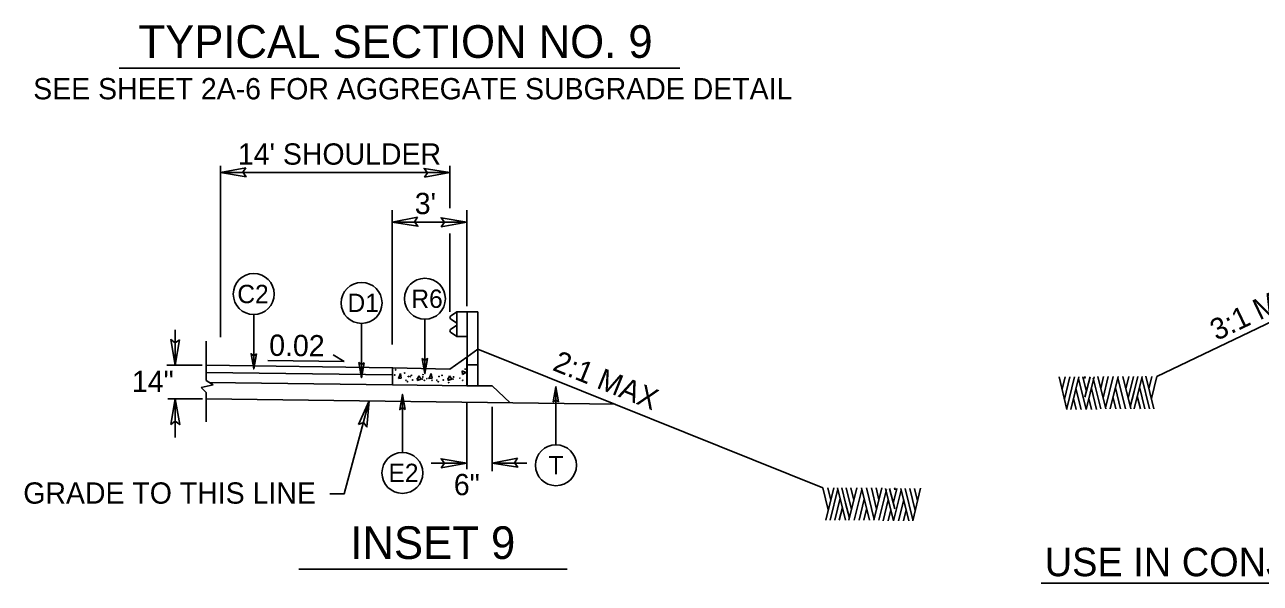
# Model space of a CAD drawing. Extents: x 573748 to 574632, y -54663 to -53209.
# Drawn here: x 574021.1 to 574108.2, y -54255.2 to -54215.9 of the extents above; entities that cross this region are included whole.
import ezdxf

# ---------------------------------------------------------------- set-up
doc = ezdxf.new("R2010")
doc.units = 0
for name, color, linetype in [('Prop Dimension', 7, 'Continuous'), ('Prop Dimension Text', 7, 'Continuous'), ('Prop Terminator CELL', 7, 'Continuous'), ('Typical Arrow Superelevation CELL', 7, 'Continuous'), ('Typical Curb CELL', 7, 'Continuous'), ('Typical Guardrail CELL', 7, 'Continuous'), ('Typical Hinge Slope Arterial CELL', 7, 'Continuous'), ('Typical ID Circle CELL', 7, 'Continuous'), ('Typical Pavement Slope CELL', 7, 'Continuous'), ('Typical Slope Point Local CELL', 7, 'Continuous'), ('Typical Terminator CELL', 7, 'Continuous'), ('Typical Text General CELL', 7, 'Continuous'), ('Typical Text ID Circle CELL', 7, 'Continuous'), ('Typical Text Label CELL', 7, 'Continuous')]:
    doc.layers.add(name, color=color, linetype=linetype)

msp = doc.modelspace()

# ---------------------------------------------------------------- linework, layer by layer
at = {"layer": 'Prop Dimension'}
for p, q in [((574034.928, -54237.862), (574034.928, -54225.799)), ((574051.103, -54228.794), (574051.103, -54225.799)), ((574034.928, -54226.281), (574051.103, -54226.281)), ((574047.036, -54238.382), (574047.036, -54228.937)), ((574052.294, -54235.69), (574052.294, -54228.937)), ((574047.036, -54229.764), (574052.294, -54229.764)), ((574051.103, -54236.089), (574051.103, -54230.577)), ((574031.746, -54237.345), (574031.746, -54239.849)), ((574033.923, -54238.16), (574033.923, -54240.935)), ((574031.151, -54239.849), (574033.652, -54239.849)), ((574034.429, -54241.231), (574033.564, -54241.428)), ((574033.564, -54241.428), (574033.923, -54241.779)), ((574033.923, -54240.935), (574034.429, -54241.231)), ((574031.216, -54242.216), (574033.673, -54242.216)), ((574031.746, -54242.216), (574031.746, -54244.939)), ((574033.923, -54241.779), (574033.923, -54243.831)), ((574052.294, -54247.175), (574052.294, -54242.481)), ((574054.075, -54247.322), (574054.075, -54242.775)), ((574049.783, -54246.736), (574052.294, -54246.736)), ((574054.075, -54246.736), (574056.516, -54246.736))]:
    msp.add_line(p, q, dxfattribs=at)
msp.add_lwpolyline([(574042.641, -54248.905), (574043.662, -54248.905), (574045.423, -54242.368)], dxfattribs=at)
at = {"layer": 'Prop Terminator CELL'}
for points in [[(574036.725, -54225.947), (574034.928, -54226.281), (574036.743, -54226.577), (574036.509, -54226.26)], [(574049.307, -54226.614), (574051.103, -54226.281), (574049.288, -54225.984), (574049.523, -54226.301)], [(574048.833, -54229.431), (574047.036, -54229.764), (574048.851, -54230.061), (574048.617, -54229.744)], [(574050.498, -54230.097), (574052.294, -54229.764), (574050.48, -54229.467), (574050.714, -54229.784)], [(574032.056, -54238.049), (574031.746, -54239.849), (574031.426, -54238.039), (574031.746, -54238.269)], [(574031.436, -54244.016), (574031.746, -54242.216), (574032.066, -54244.026), (574031.746, -54243.796)], [(574044.655, -54244.026), (574045.423, -54242.368), (574045.261, -54244.2), (574045.011, -54243.894)], [(574050.498, -54247.07), (574052.294, -54246.736), (574050.48, -54246.44), (574050.714, -54246.757)], [(574055.871, -54246.403), (574054.075, -54246.736), (574055.889, -54247.033), (574055.655, -54246.716)]]:
    msp.add_lwpolyline(points, close=True, dxfattribs=at)
at = {"layer": 'Typical Arrow Superelevation CELL'}
for q in [(574038.268, -54239.526), (574042.875, -54239.124)]:
    msp.add_line((574043.662, -54239.591), q, dxfattribs=at)
at = {"layer": 'Typical Curb CELL'}
for p, q in [((574052.294, -54239.272), (574053.079, -54238.708)), ((574051.103, -54240.129), (574052.294, -54239.272)), ((574052.294, -54241.296), (574052.294, -54239.272)), ((574047.06, -54240.024), (574047.06, -54240.024)), ((574047.06, -54241.228), (574047.06, -54240.055)), ((574047.078, -54240.025), (574051.103, -54240.129)), ((574047.471, -54240.789), (574047.621, -54240.443)), ((574047.681, -54240.771), (574047.471, -54240.789)), ((574047.621, -54240.443), (574047.681, -54240.771)), ((574048.798, -54240.936), (574048.906, -54240.605)), ((574049.085, -54240.822), (574048.798, -54240.936)), ((574048.906, -54240.605), (574049.085, -54240.822)), ((574049.637, -54240.789), (574049.785, -54240.443)), ((574049.845, -54240.771), (574049.637, -54240.789)), ((574049.785, -54240.443), (574049.845, -54240.771)), ((574050.962, -54240.936), (574051.071, -54240.605)), ((574051.249, -54240.822), (574050.962, -54240.936)), ((574051.071, -54240.605), (574051.249, -54240.822)), ((574051.964, -54240.235), (574051.993, -54240.497)), ((574052.231, -54240.364), (574051.964, -54240.235)), ((574051.993, -54240.497), (574052.231, -54240.364)), ((574052.294, -54241.296), (574047.06, -54241.228)), ((574052.294, -54241.296), (574054.075, -54241.296))]:
    msp.add_line(p, q, dxfattribs=at)
msp.add_ellipse((574047.078, -54240.055), major_axis=(0, -0.0301), ratio=0.6, start_param=3.105848, end_param=4.712389, dxfattribs=at)
for centre in [(574047.215, -54240.538), (574047.281, -54240.176), (574047.917, -54240.392), (574048.175, -54240.639), (574048.306, -54240.645), (574048.392, -54240.557), (574048.81, -54240.777), (574049.166, -54240.824), (574049.196, -54240.678), (574049.214, -54240.507), (574049.479, -54240.788), (574049.641, -54240.76), (574050.34, -54240.639), (574050.557, -54240.557), (574050.975, -54240.777), (574051.331, -54240.824), (574051.361, -54240.678), (574051.806, -54240.76), (574052.182, -54240.118), (574048.02, -54240.907), (574048.118, -54241.005), (574048.474, -54240.89), (574049.312, -54240.92), (574049.849, -54240.907), (574050.185, -54240.907), (574050.282, -54241.005), (574050.639, -54240.89), (574051.025, -54241.071), (574052.014, -54240.907)]:
    msp.add_ellipse(centre, major_axis=(0, 0.0232), ratio=0.6, dxfattribs=at)
at = {"layer": 'Typical Guardrail CELL'}
for p, q in [((574051.587, -54236.089), (574051.153, -54236.394)), ((574052.333, -54236.089), (574051.587, -54236.089)), ((574051.587, -54236.089), (574051.587, -54237.829)), ((574052.333, -54236.089), (574052.333, -54239.818)), ((574052.333, -54236.089), (574053.079, -54236.089)), ((574053.079, -54236.089), (574053.079, -54239.818)), ((574051.587, -54236.889), (574051.153, -54236.585)), ((574051.587, -54237.029), (574051.153, -54237.334)), ((574051.587, -54236.959), (574051.587, -54236.889)), ((574051.587, -54236.959), (574051.587, -54237.029)), ((574051.587, -54237.829), (574051.153, -54237.525)), ((574052.333, -54237.829), (574051.587, -54237.829)), ((574052.333, -54239.818), (574053.079, -54239.818)), ((574052.333, -54239.818), (574052.333, -54241.33)), ((574053.079, -54239.818), (574053.079, -54241.33))]:
    msp.add_line(p, q, dxfattribs=at)
for centre, start, end in [((574051.219, -54236.489), 125.00297, 235.0112), ((574051.22, -54237.429), 125.0059, 235.0366)]:
    msp.add_arc(centre, 0.116, start, end, dxfattribs=at)
at = {"layer": 'Typical Hinge Slope Arterial CELL'}
for p, q in [((574116.259, -54233.302), (574100.923, -54240.643)), ((574053.079, -54238.708), (574077.393, -54248.493))]:
    msp.add_line(p, q, dxfattribs=at)
at = {"layer": 'Typical ID Circle CELL'}
for p, q in [((574037.283, -54236.278), (574037.283, -54240.104)), ((574044.88, -54236.901), (574044.88, -54240.727)), ((574049.344, -54236.61), (574049.344, -54240.437)), ((574058.58, -54245.453), (574058.58, -54241.369)), ((574047.761, -54245.992), (574047.761, -54241.909))]:
    msp.add_line(p, q, dxfattribs=at)
for centre in [(574037.283, -54234.835), (574049.344, -54235.168), (574044.88, -54235.459), (574047.761, -54247.435), (574058.58, -54246.895)]:
    msp.add_circle(centre, 1.443, dxfattribs=at)
at = {"layer": 'Typical Pavement Slope CELL'}
for p, q in [((574033.919, -54239.849), (574047.06, -54240.024)), ((574033.923, -54240.363), (574047.04, -54240.537)), ((574034.129, -54241.055), (574047.06, -54241.226)), ((574055.358, -54242.5), (574054.075, -54241.296)), ((574033.923, -54242.216), (574062.745, -54242.598))]:
    msp.add_line(p, q, dxfattribs=at)
at = {"layer": 'Typical Slope Point Local CELL'}
for p, q in [((574094.596, -54242.961), (574094.033, -54240.665)), ((574094.246, -54241.543), (574094.458, -54240.672)), ((574094.415, -54242.23), (574094.801, -54240.672)), ((574094.58, -54242.887), (574095.128, -54240.672)), ((574094.856, -54242.961), (574095.427, -54240.672)), ((574095.939, -54242.961), (574095.399, -54240.79)), ((574095.95, -54241.639), (574095.71, -54240.672)), ((574095.82, -54240.746), (574095.848, -54240.643)), ((574095.864, -54242.104), (574096.218, -54240.672)), ((574095.864, -54240.783), (574095.887, -54240.672)), ((574095.946, -54242.961), (574096.517, -54240.672)), ((574096.986, -54242.924), (574096.45, -54240.753)), ((574097.324, -54242.924), (574096.761, -54240.643)), ((574096.974, -54241.484), (574097.179, -54240.643)), ((574097.135, -54242.149), (574097.505, -54240.643)), ((574097.309, -54242.857), (574097.856, -54240.643)), ((574097.643, -54242.924), (574098.21, -54240.643)), ((574098.722, -54242.924), (574098.183, -54240.746)), ((574099.088, -54242.924), (574098.525, -54240.643)), ((574098.738, -54241.514), (574098.95, -54240.643)), ((574098.903, -54242.171), (574099.285, -54240.643)), ((574099.32, -54241.706), (574099.58, -54240.643)), ((574099.32, -54242.924), (574099.887, -54240.643)), ((574100.419, -54242.924), (574099.872, -54240.709)), ((574100.722, -54242.924), (574100.159, -54240.628)), ((574100.368, -54241.506), (574100.58, -54240.643)), ((574100.541, -54242.193), (574100.923, -54240.643)), ((574095.588, -54242.961), (574095.226, -54241.477)), ((574095.927, -54241.514), (574095.95, -54241.425)), ((574096.679, -54242.961), (574096.316, -54241.477)), ((574098.376, -54242.924), (574098.009, -54241.44)), ((574099.053, -54242.783), (574099.32, -54241.706)), ((574100.084, -54242.924), (574099.706, -54241.366)), ((574095.234, -54242.961), (574095.049, -54242.193)), ((574096.324, -54242.961), (574096.139, -54242.193)), ((574098.029, -54242.924), (574097.84, -54242.134)), ((574099.765, -54242.924), (574099.545, -54242.023)), ((574077.775, -54250.043), (574077.393, -54248.493)), ((574077.594, -54250.774), (574078.157, -54248.478)), ((574077.948, -54249.356), (574077.735, -54248.493)), ((574077.897, -54250.774), (574078.444, -54248.559)), ((574078.995, -54250.774), (574078.428, -54248.493)), ((574078.995, -54249.556), (574078.735, -54248.493)), ((574079.413, -54250.021), (574079.031, -54248.493)), ((574079.227, -54250.774), (574079.79, -54248.493)), ((574079.578, -54249.364), (574079.365, -54248.493)), ((574079.594, -54250.774), (574080.133, -54248.596)), ((574080.672, -54250.774), (574080.105, -54248.493)), ((574081.007, -54250.707), (574080.46, -54248.493)), ((574081.18, -54249.998), (574080.81, -54248.493)), ((574080.991, -54250.774), (574081.554, -54248.493)), ((574081.342, -54249.334), (574081.137, -54248.493)), ((574081.33, -54250.774), (574081.865, -54248.603)), ((574082.369, -54250.81), (574081.798, -54248.522)), ((574082.452, -54249.954), (574082.098, -54248.522)), ((574082.365, -54249.489), (574082.605, -54248.522)), ((574082.377, -54250.81), (574082.916, -54248.64)), ((574082.452, -54248.633), (574082.428, -54248.522)), ((574082.495, -54248.596), (574082.468, -54248.493)), ((574083.46, -54250.81), (574082.889, -54248.522)), ((574083.735, -54250.737), (574083.188, -54248.522)), ((574083.901, -54250.08), (574083.515, -54248.522)), ((574083.72, -54250.81), (574084.283, -54248.515)), ((574084.07, -54249.393), (574083.857, -54248.522)), ((574078.231, -54250.774), (574078.609, -54249.216)), ((574079.263, -54250.633), (574078.995, -54249.556)), ((574079.94, -54250.774), (574080.306, -54249.29)), ((574081.637, -54250.81), (574081.999, -54249.327)), ((574082.389, -54249.364), (574082.365, -54249.275)), ((574082.727, -54250.81), (574083.09, -54249.327)), ((574078.55, -54250.774), (574078.771, -54249.873)), ((574080.287, -54250.774), (574080.476, -54249.984)), ((574081.991, -54250.81), (574082.176, -54250.043)), ((574083.082, -54250.81), (574083.267, -54250.043))]:
    msp.add_line(p, q, dxfattribs=at)
at = {"layer": 'Typical Terminator CELL'}
for points in [[(574037.464, -54239.05), (574037.283, -54240.104), (574037.095, -54239.044), (574037.283, -54239.179)], [(574045.061, -54239.673), (574044.88, -54240.727), (574044.692, -54239.667), (574044.88, -54239.802)], [(574049.162, -54239.382), (574049.344, -54240.437), (574049.532, -54239.376), (574049.344, -54239.511)], [(574058.761, -54242.424), (574058.58, -54241.369), (574058.392, -54242.43), (574058.58, -54242.295)], [(574047.942, -54242.963), (574047.761, -54241.909), (574047.573, -54242.969), (574047.761, -54242.834)]]:
    msp.add_lwpolyline(points, close=True, dxfattribs=at)
at = {"layer": 'Typical Text General CELL'}
msp.add_line((574151.539, -54255.207), (574092.764, -54255.207), dxfattribs=at)
at = {"layer": 'Typical Text Label CELL'}
for p, q in [((574027.802, -54218.92), (574067.313, -54218.92)), ((574040.467, -54254.215), (574059.375, -54254.215))]:
    msp.add_line(p, q, dxfattribs=at)

# ---------------------------------------------------------------- texts
at = {"layer": 'Prop Dimension'}
msp.add_text('GRADE TO THIS LINE', height=1.5, dxfattribs=at).set_placement((574021.038, -54249.601))
at = {"layer": 'Prop Dimension Text'}
for s, height, p in [('TYPICAL SECTION NO. 9', 2.3, (574029.16, -54218.2)), ("14' SHOULDER", 1.5, (574036.164, -54225.723)), ("3'", 1.5, (574048.628, -54229.207)), ('14"', 1.5, (574028.699, -54241.739)), ('6"', 1.5, (574051.383, -54249.004)), ('INSET 9', 2.3, (574044.09, -54253.495))]:
    msp.add_text(s, height=height, dxfattribs=at).set_placement(p)
for s, rotation, p in [('3:1 MAX', 25.5792, (574105.141, -54238.152)), ('0.02', 359.31258, (574038.364, -54239.185)), ('2:1 MAX', 338.07795, (574058.26, -54240.17))]:
    msp.add_text(s, height=1.5, rotation=rotation, dxfattribs=at).set_placement(p)
at = {"layer": 'Typical Text General CELL'}
for s, height, p in [('SEE SHEET 2A-6 FOR AGGREGATE SUBGRADE DETAIL', 1.5, (574021.738, -54221.122)), ('USE IN CONJUNCTION WITH T.S. #9 & 9A', 2, (574093.025, -54254.71))]:
    msp.add_text(s, height=height, dxfattribs=at).set_placement(p)
at = {"layer": 'Typical Text ID Circle CELL'}
for s, height, p in [('C2', 1.2912, (574036.125, -54235.478)), ('R6', 1.2912, (574048.39, -54235.81)), ('D1', 1.2912, (574043.888, -54236.101)), ('E2', 1.2912, (574046.779, -54248.078)), ('T', 1.291, (574058.058, -54247.538))]:
    msp.add_text(s, height=height, dxfattribs=at).set_placement(p)

doc.saveas('drawing.dxf')
